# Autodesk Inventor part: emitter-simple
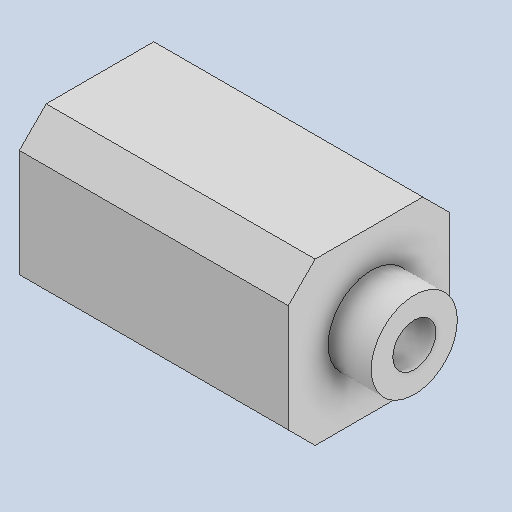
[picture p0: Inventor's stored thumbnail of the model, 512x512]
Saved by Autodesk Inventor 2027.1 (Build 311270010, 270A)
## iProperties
Created: 2026-07
Part Number: emitter-simple
Material: Generic
Document SubType Name: Modeling
Designer: dunge
Density: 1 g/cm^3
Appearance: Default
Author: dunge
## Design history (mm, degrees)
sketch "Sketch1"
  geometry: L1 (16.089, 9.798)-(-15.661, 9.798); L2 (-15.661, 9.798)-(-15.661, -9.252); L3 (-15.661, -9.252)-(16.089, -9.252); L4 (16.089, -9.252)-(16.089, 9.798); 1 further point
  constraints: 8 end point, 2 parallel, 1 horizontal, 1 perpendicular
  dimensions: "d0" = 19.05 distance of L3.end L1.start; "d1" = 31.75 distance of L1.start L1.end
extrude "Extrusion1" new body sketch "Sketch1" distance "d2" = 19.05; taper "d3" = 0 deg
sketch "Sketch2"
  geometry: C1 r 5.08 at (9.798, 9.516); 1 further point
  constraints: 1 centre point
  dimensions: "d4" = 10.16 diameter of C1
extrude "Extrusion2" join sketch "Sketch2" distance "d5" = 5.08; taper "d6" = 0 deg
chamfer "Chamfer1" distance "d7" = 3.175; stored, may be unused: second distance "d8" = 3.175, angle "d9" = 45 deg
sketch "Sketch3"
  geometry: C1 r 2.54 at (0, 0); 1 further point
  constraints: 1 centre point
  dimensions: "d10" = 5.08 diameter of C1
extrude "Extrusion3" cut sketch "Sketch3" distance "d11" = 16.1925; taper "d12" = 0 deg
body "Solid1"
